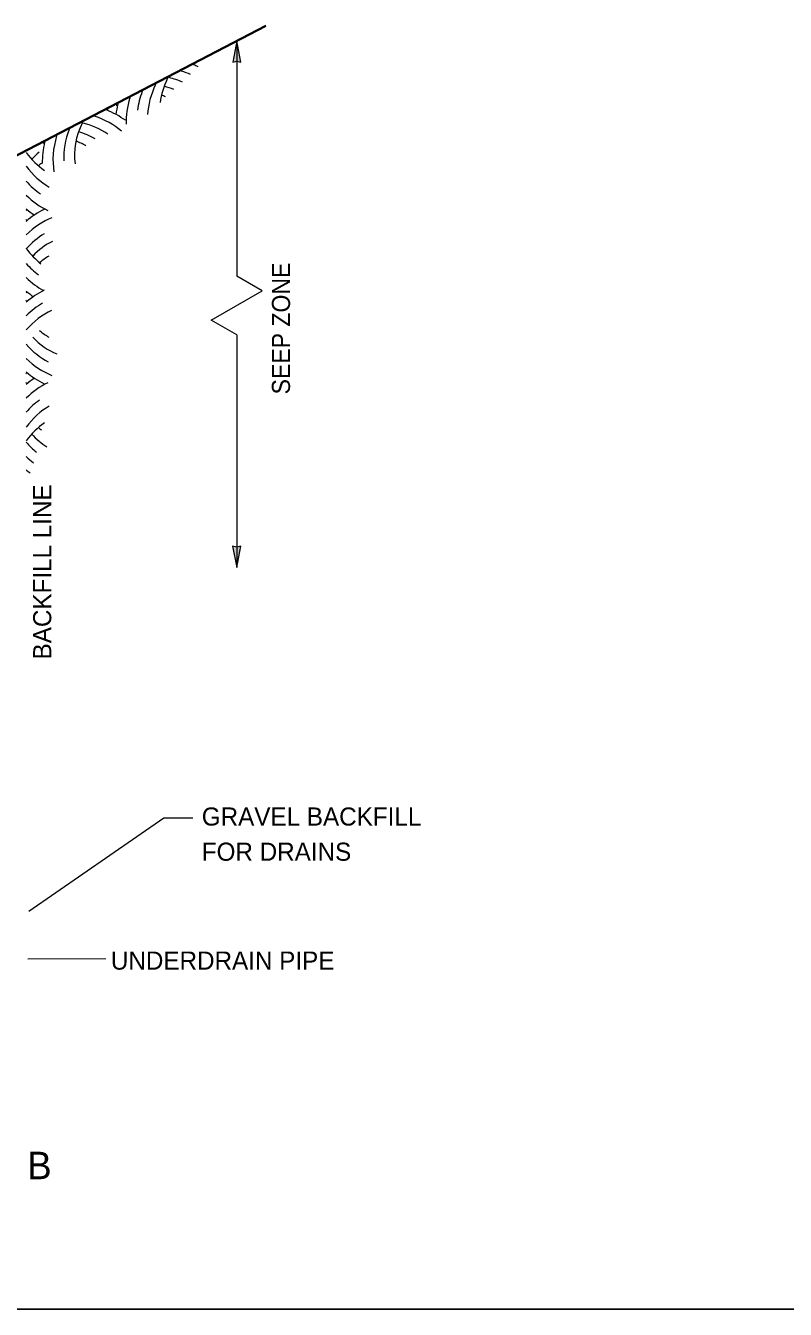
# Model space of a CAD drawing. Extents: x 17672 to 18472, y -9785 to -9267.
# Drawn here: x 17874.3 to 18022.2, y -9784.8 to -9534.7 of the extents above; entities that cross this region are included whole.
import ezdxf
from ezdxf.enums import TextEntityAlignment as Align

# ---------------------------------------------------------------- set-up
doc = ezdxf.new("R2010")
doc.units = 0
doc.header["$LTSCALE"] = 1.4
for name, color, linetype, lineweight in [('1', 7, 'Continuous', 13), ('15', 7, 'Continuous', 13), ('16', 7, 'Continuous', 13), ('20', 7, 'Continuous', 25), ('30', 7, 'Continuous', 25)]:
    doc.layers.add(name, color=color, linetype=linetype, lineweight=lineweight)

msp = doc.modelspace()

# ---------------------------------------------------------------- hatches: boundary and pattern name
at = {"layer": '16'}
for points in [[(17915.372, -9537.676), (17914.59, -9541.814), (17915.372, -9541.627), (17916.193, -9541.814)], [(17915.372, -9640.246), (17916.154, -9636.108), (17915.372, -9636.295), (17914.551, -9636.108)]]:
    msp.add_hatch(color=256, dxfattribs=at).paths.add_polyline_path(points)

# ---------------------------------------------------------------- linework, layer by layer
at = {"layer": '1', "lineweight": 35}
msp.add_line((17921.042, -9534.724), (17824.355, -9585.104), dxfattribs=at)
at = {"layer": '1'}
for centre, major_axis, start_param, end_param in [((17891.377, -9561.716), (21.721, 11.27), 0.5089521, 0.6048262), ((17891.377, -9561.716), (23.677, 12.286), 0.5035044, 0.5487601), ((17919.373, -9547.189), (-17.807, -9.24), 5.5176695, 5.8182486), ((17891.377, -9561.716), (19.764, 10.255), 0.5214974, 0.6750191), ((17917.02, -9548.41), (-19.764, -10.255), 5.6081662, 5.8162629), ((17917.02, -9548.41), (-17.807, -9.24), 5.5176695, 5.890171), ((17889.221, -9562.913), (17.807, 9.24), 0.5121332, 0.5623339), ((17891.377, -9561.716), (17.807, 9.24), 0.545492, 0.6663322), ((17865.287, -9548.495), (25.27, 13.112), 5.5360053, 5.5474825), ((17917.02, -9548.41), (-23.677, -12.286), 5.7344252, 5.8300808), ((17904.289, -9528.257), (-25.27, -13.112), 0.7357028, 0.74718), ((17917.02, -9548.41), (-21.721, -11.27), 5.6783592, 5.9462814), ((17874.435, -9570.507), (21.721, 11.27), 0.2884398, 0.6048262), ((17874.435, -9570.507), (23.677, 12.286), 0.3472839, 0.5487601), ((17902.788, -9555.795), (-19.764, -10.255), 5.6081662, 5.9621663), ((17902.788, -9555.795), (-17.807, -9.24), 5.5176695, 6.0355169), ((17874.435, -9570.507), (17.807, 9.24), 0.4330369, 0.6499807), ((17874.435, -9570.507), (19.764, 10.255), 0.3642278, 0.6750191), ((17902.788, -9555.795), (-23.677, -12.286), 5.7344252, 5.9365445), ((17890.057, -9535.642), (-25.27, -13.112), 0.7357028, 0.74718), ((17902.788, -9555.795), (-21.721, -11.27), 5.6783592, 6.0528283), ((17872.279, -9571.704), (17.807, 9.24), 0.4054458, 0.5431634), ((17884.39, -9544.969), (0, -20.062), 5.5176695, 5.8182486), ((17884.39, -9576.51), (0, 20.062), 0.545492, 0.6663322), ((17884.39, -9547.62), (0, -20.062), 5.5176695, 5.890171), ((17884.459, -9578.975), (0, 20.062), 0.5121332, 0.5623339), ((17884.39, -9547.62), (0, -22.266), 5.6081662, 5.8162629), ((17884.39, -9547.62), (0, -24.471), 5.6783592, 5.9462814), ((17884.39, -9547.62), (0, -26.675), 5.7344252, 5.8300808), ((17884.39, -9595.597), (0, 26.675), 0.3472839, 0.5487601), ((17860.638, -9549.638), (0, -28.469), 0.7357028, 0.74718), ((17884.39, -9595.597), (0, 24.471), 0.2884398, 0.6048262), ((17860.638, -9593.579), (0, 28.469), 5.5360053, 5.5474825), ((17884.39, -9595.597), (0, 22.266), 0.4190168, 0.6750191), ((17884.39, -9563.655), (0, -20.062), 5.5176695, 5.7663747), ((17884.39, -9595.597), (0, 20.062), 0.3470478, 0.6499807), ((17884.39, -9563.655), (0, -22.266), 5.6081662, 5.7860327), ((17884.459, -9598.062), (0, 20.062), 0.4054458, 0.5431634), ((17884.39, -9563.655), (0, -24.471), 5.6783592, 5.8969202), ((17884.39, -9611.345), (0, 26.675), 0.3466408, 0.5487601), ((17884.39, -9563.655), (0, -26.675), 5.7344252, 5.8190718), ((17860.638, -9565.673), (0, -28.469), 0.7357028, 0.74718), ((17860.638, -9609.326), (0, 28.469), 5.5360053, 5.5474825), ((17884.39, -9611.345), (0, 24.471), 0.3965617, 0.6048262), ((17884.39, -9611.345), (0, 22.266), 0.321019, 0.6750191), ((17884.39, -9579.402), (0, -20.062), 5.6332046, 5.999911), ((17884.459, -9576.938), (0, -20.062), 5.7400219, 5.8777396), ((17884.39, -9579.402), (0, -22.266), 5.6081662, 5.9189575), ((17884.39, -9579.402), (0, -24.471), 5.6783592, 5.9947455), ((17884.39, -9579.402), (0, -26.675), 5.7344252, 5.9359014), ((17860.638, -9581.421), (0, -28.469), 0.7357028, 0.74718), ((17884.39, -9627.379), (0, 26.675), 0.4531045, 0.5487601), ((17860.638, -9625.361), (0, 28.469), 5.5360053, 5.5474825), ((17884.39, -9627.379), (0, 24.471), 0.3369039, 0.6048262), ((17884.39, -9627.379), (0, 22.266), 0.481461, 0.6750191), ((17884.39, -9627.379), (0, 20.062), 0.3930143, 0.7655158), ((17884.39, -9630.03), (0, 20.062), 0.4649367, 0.7655158), ((17884.459, -9596.024), (0, -20.062), 5.7208514, 5.7710521), ((17884.39, -9598.489), (0, -22.266), 5.6081662, 5.761688), ((17884.39, -9598.489), (0, -20.062), 5.6168531, 5.8558303), ((17884.39, -9598.489), (0, -24.471), 5.6783592, 5.7742332), ((17884.39, -9598.489), (0, -26.675), 5.7344252, 5.7796809)]:
    msp.add_ellipse(centre, major_axis=major_axis, ratio=0.719298, start_param=start_param, end_param=end_param, dxfattribs=at)
at = {"layer": '15'}
for p, q in [((17915.372, -9537.676), (17915.372, -9583.498)), ((17915.372, -9594.964), (17915.372, -9640.246)), ((17901.176, -9689.067), (17874.925, -9707.278)), ((17906.857, -9689.067), (17901.176, -9689.067)), ((17889.889, -9716.491), (17874.683, -9716.55))]:
    msp.add_line(p, q, dxfattribs=at)
msp.add_lwpolyline([(17915.372, -9594.964), (17910.401, -9592.103), (17920.342, -9586.358), (17915.372, -9583.498)], dxfattribs=at)
at = {"layer": '16'}
for points in [[(17915.372, -9537.676), (17914.59, -9541.814), (17915.372, -9541.627), (17916.193, -9541.814)], [(17915.372, -9640.246), (17916.154, -9636.108), (17915.372, -9636.295), (17914.551, -9636.108)]]:
    msp.add_lwpolyline(points, close=True, dxfattribs=at)
at = {"layer": '30'}
msp.add_line((17671.774, -9784.752), (18471.773, -9784.752), dxfattribs=at)

# ---------------------------------------------------------------- texts
at = {"layer": '20', "width": 0.95}
msp.add_text('SEEP ZONE', height=3.529, rotation=90, dxfattribs=at).set_placement((17925.759, -9606.54))
at = {"layer": '20'}
msp.add_text('BACKFILL LINE', height=3.529, rotation=90, dxfattribs=at).set_placement((17879.271, -9658.163))
for s, p in [('GRAVEL BACKFILL', (17908.575, -9690.528)), ('FOR DRAINS', (17908.575, -9697.379)), ('UNDERDRAIN PIPE', (17890.874, -9718.585))]:
    msp.add_text(s, height=3.529, dxfattribs=at).set_placement(p)
msp.add_text('CONDITION B', height=5.348, dxfattribs=at).set_placement((17855.903, -9759.411), align=Align.CENTER)

doc.saveas('drawing.dxf')
